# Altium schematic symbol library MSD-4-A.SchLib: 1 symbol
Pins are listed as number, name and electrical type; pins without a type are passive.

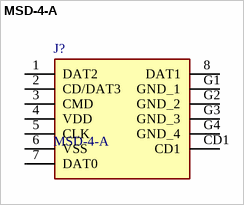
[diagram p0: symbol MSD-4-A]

## MSD-4-A
designator J?
Memory Card Connectors 9 Positions, Push In, Auto Eject Out, SMT, 1.8 mm Height Above Board,; Manufacturer_Name: Same Sky; Geometry.Height: 2mm
footprint MSD4A
pins: 1 DAT2, 2 CD/DAT3, 3 CMD, 4 VDD, 5 CLK, 6 VSS, 7 DAT0, 8 DAT1, CD1, G1 GND_1, G2 GND_2, G3 GND_3, G4 GND_4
